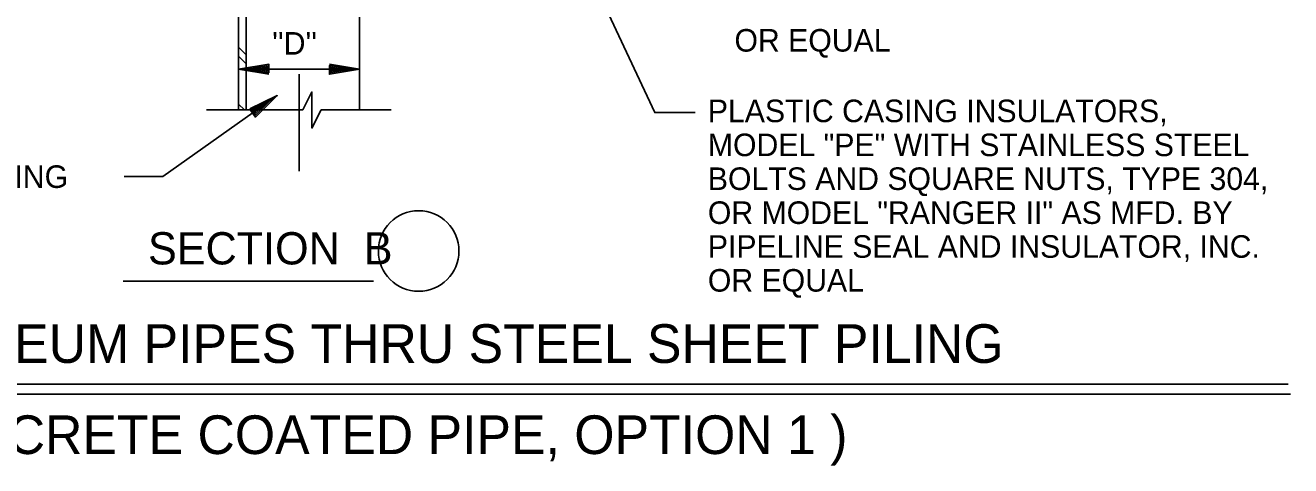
# Model space of a CAD drawing. Extents: x 22422.9 to 22498.9, y 22369.6 to 22415.
# Drawn here: x 22465.87 to 22476.33, y 22380.91 to 22384.56 of the extents above; entities that cross this region are included whole.
import ezdxf

# ---------------------------------------------------------------- set-up
doc = ezdxf.new("R2010")
doc.units = 0
for name, color, linetype in [('Level 1', 7, 'Continuous'), ('Level 10', 7, 'Continuous'), ('Level 2', 7, 'Continuous'), ('Level 3', 7, 'Continuous'), ('Level 4', 7, 'Continuous'), ('Level 8', 7, 'Continuous')]:
    doc.layers.add(name, color=color, linetype=linetype)

msp = doc.modelspace()

# ---------------------------------------------------------------- linework, layer by layer
at = {"layer": 'Level 1'}
for p, q in [((22468.63, 22384.195), (22467.63, 22384.195)), ((22468.06, 22384.195), (22468.06, 22384.195)), ((22468.13, 22384.195), (22468.13, 22384.195)), ((22468.13, 22384.195), (22468.13, 22384.195)), ((22468.199, 22384.195), (22468.199, 22384.195)), ((22468.13, 22383.351), (22468.13, 22384.154)), ((22467.892, 22383.936), (22467.892, 22383.936)), ((22467.949, 22383.976), (22467.949, 22383.976)), ((22467.364, 22383.857), (22468.162, 22383.857)), ((22468.311, 22383.857), (22468.891, 22383.857))]:
    msp.add_line(p, q, dxfattribs=at)
msp.add_lwpolyline([(22468.162, 22383.857), (22468.236, 22384.007), (22468.236, 22383.707), (22468.311, 22383.857)], dxfattribs=at)
at = {"layer": 'Level 10'}
for p, q in [((22466.675, 22382.441), (22468.746, 22382.441)), ((22459.986, 22381.589), (22476.306, 22381.589)), ((22459.986, 22381.505), (22476.327, 22381.505))]:
    msp.add_line(p, q, dxfattribs=at)
at = {"layer": 'Level 2'}
for p, q in [((22467.63, 22383.857), (22467.63, 22386.967)), ((22467.692, 22383.857), (22467.692, 22386.967)), ((22468.63, 22383.857), (22468.63, 22386.967))]:
    msp.add_line(p, q, dxfattribs=at)
for points in [[(22471.405, 22383.835), (22471.07, 22383.835), (22470.624, 22384.79)], [(22467.879, 22384.153), (22467.63, 22384.195), (22467.879, 22384.236), (22467.879, 22384.165), (22467.699, 22384.195), (22467.868, 22384.223), (22467.868, 22384.177), (22467.766, 22384.195), (22467.858, 22384.209), (22467.858, 22384.191), (22467.835, 22384.195)], [(22468.38, 22384.236), (22468.63, 22384.195), (22468.38, 22384.153), (22468.38, 22384.224), (22468.56, 22384.195), (22468.391, 22384.167), (22468.391, 22384.212), (22468.494, 22384.195), (22468.402, 22384.18), (22468.402, 22384.199), (22468.424, 22384.195)], [(22466.683, 22383.307), (22467.004, 22383.307), (22467.949, 22383.976)], [(22467.722, 22383.866), (22467.949, 22383.976), (22467.769, 22383.798), (22467.728, 22383.856), (22467.892, 22383.936), (22467.77, 22383.815), (22467.744, 22383.852), (22467.838, 22383.898), (22467.771, 22383.832), (22467.761, 22383.848), (22467.781, 22383.858)]]:
    msp.add_lwpolyline(points, dxfattribs=at)
at = {"layer": 'Level 3'}
msp.add_circle((22469.118, 22382.69), 0.333, dxfattribs=at)
at = {"layer": 'Level 8'}
for p, q in [((22467.63, 22384.195), (22467.63, 22384.195)), ((22467.699, 22384.195), (22467.699, 22384.195)), ((22468.56, 22384.195), (22468.56, 22384.195)), ((22468.63, 22384.195), (22468.63, 22384.195))]:
    msp.add_line(p, q, dxfattribs=at)
for points in [[(22467.692, 22384.314), (22467.63, 22384.376)], [(22467.692, 22384.239), (22467.63, 22384.301)], [(22467.678, 22383.857), (22467.63, 22383.905)]]:
    msp.add_lwpolyline(points, dxfattribs=at)

# ---------------------------------------------------------------- texts
at = {"layer": 'Level 3'}
for s, height, p in [('SECTION  B', 0.2667, (22466.881, 22382.579)), ('TYPICAL GAS AND PETROLEUM PIPES THRU STEEL SHEET PILING', 0.32, (22460.115, 22381.764)), ('( OTHER THAN CONCRETE COATED PIPE, OPTION 1 )', 0.32, (22461.608, 22381.01))]:
    msp.add_text(s, height=height, dxfattribs=at).set_placement(p)
at = {"layer": 'Level 4'}
for s, height, p in [("''D''", 0.1867, (22467.907, 22384.315)), ('OR EQUAL', 0.1867, (22471.729, 22384.34)), ('PLASTIC CASING INSULATORS,', 0.18667, (22471.509, 22383.756)), ('MODEL "PE" WITH STAINLESS STEEL', 0.18667, (22471.509, 22383.475)), ('STEEL SHEET PILING', 0.18667, (22463.64, 22383.212)), ('BOLTS AND SQUARE NUTS, TYPE 304,', 0.18667, (22471.509, 22383.195)), ('OR MODEL "RANGER II" AS MFD. BY', 0.18667, (22471.509, 22382.914)), ('PIPELINE SEAL AND INSULATOR, INC.', 0.18667, (22471.509, 22382.634)), ('OR EQUAL', 0.1867, (22471.509, 22382.354))]:
    msp.add_text(s, height=height, dxfattribs=at).set_placement(p)

doc.saveas('drawing.dxf')
